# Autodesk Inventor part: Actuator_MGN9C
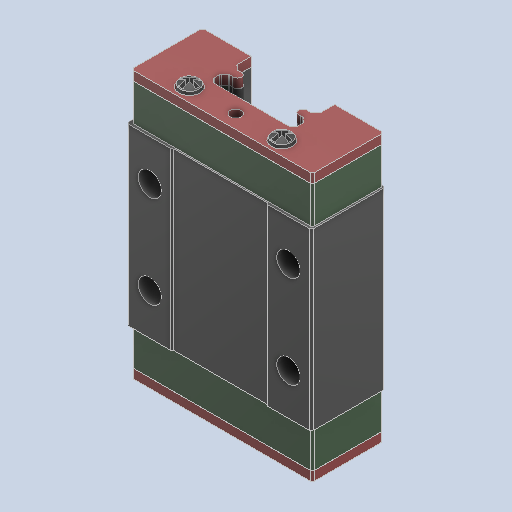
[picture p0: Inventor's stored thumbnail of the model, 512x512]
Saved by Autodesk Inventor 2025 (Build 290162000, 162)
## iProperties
Created: 2000-04
Part Number: Actuator_MGN9C
Material: Generico
Document SubType Name: Modeling
Designer: Ryzen5700u
Density: 1 g/cm^3
Appearance: Default
Author: Ryzen5700u
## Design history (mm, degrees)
feature "Solido1"
node "Solido2"
